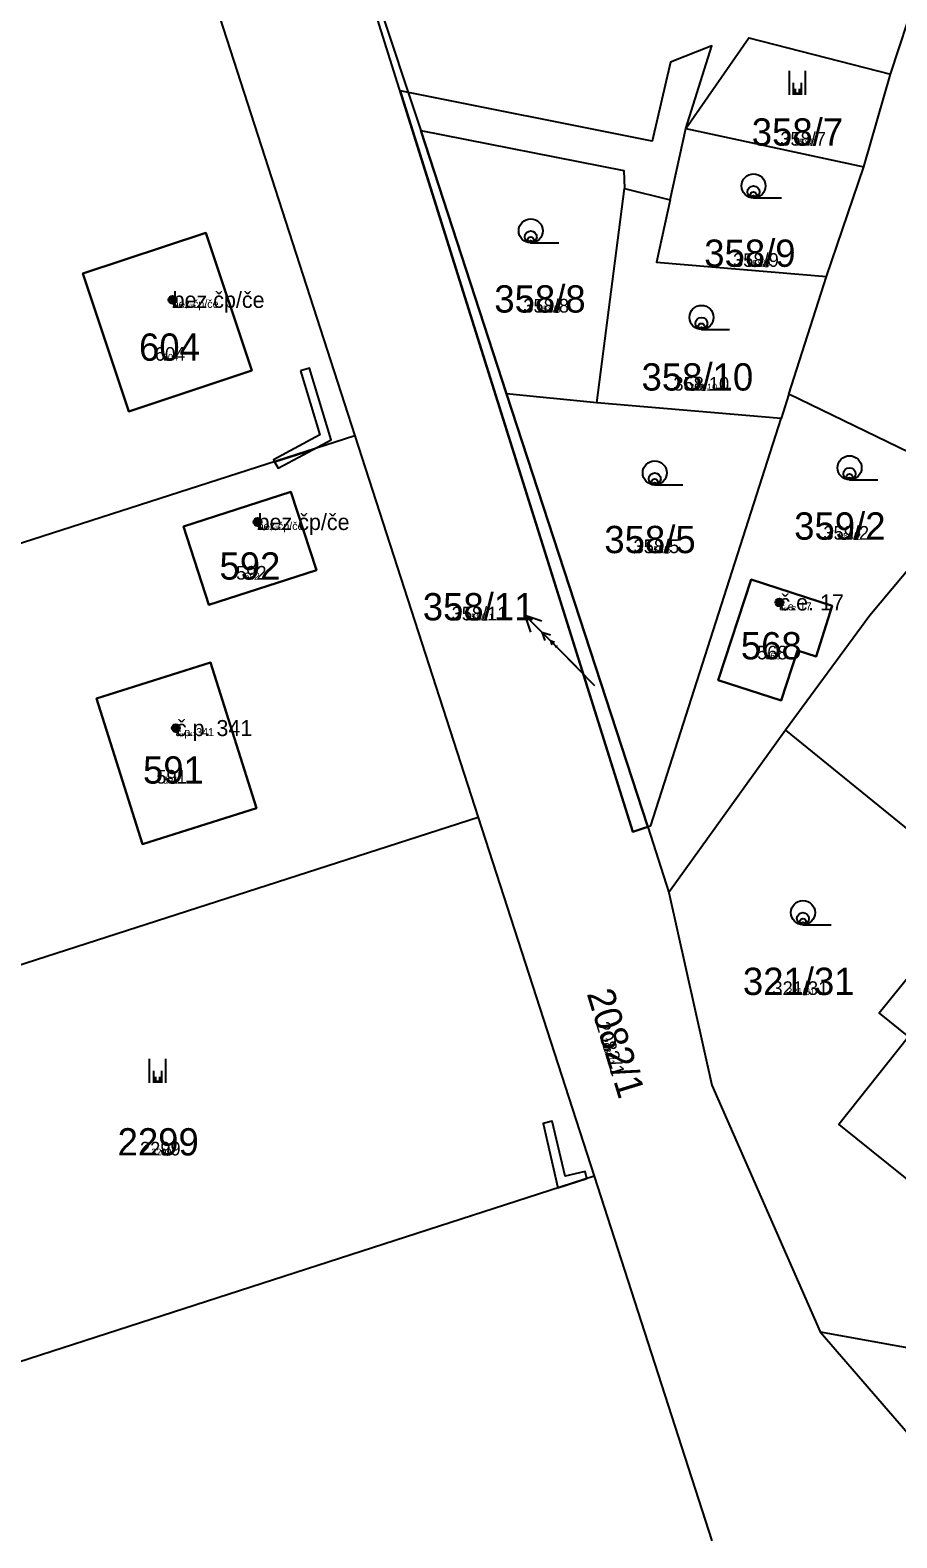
# Model space of a CAD drawing. Extents: x -744652 to -739090, y -980828 to -975855.
# Drawn here: x -742405.9 to -742351.9, y -979035.7 to -978941.8 of the extents above; entities that cross this region are included whole.
import ezdxf

# ---------------------------------------------------------------- set-up
doc = ezdxf.new("R2010")
doc.units = 0
for name, color, linetype in [('KAT_02_hranice parcel', 7, 'Continuous'), ('KAT_03_1000_st čísla parcelní', 7, 'Continuous'), ('KAT_03_1000_čísla parcelní', 7, 'Continuous'), ('KAT_03_1000_čísla popisná', 7, 'Continuous'), ('KAT_03_100_st čísla parcelní', 7, 'Continuous'), ('KAT_03_100_čísla parcelní', 7, 'Continuous'), ('KAT_03_100_čísla popisná', 7, 'Continuous'), ('KAT_03_250_st čísla parcelní', 7, 'Continuous'), ('KAT_03_250_čísla parcelní', 7, 'Continuous'), ('KAT_03_250_čísla popisná', 7, 'Continuous'), ('KAT_03_500_st čísla parcelní', 7, 'Continuous'), ('KAT_03_500_čísla parcelní', 7, 'Continuous'), ('KAT_03_500_čísla popisná', 7, 'Continuous'), ('KAT_05_1000_značky kultur', 7, 'Continuous'), ('KAT_05_100_značky kultur', 7, 'Continuous'), ('KAT_05_250_značky kultur', 7, 'Continuous'), ('KAT_05_500_značky kultur', 7, 'Continuous'), ('KAT_07_1000_značky budov', 7, 'Continuous'), ('KAT_07_100_značky budov', 7, 'Continuous'), ('KAT_07_500_značky budov', 7, 'Continuous'), ('KAT_10_věcná břemena', 7, 'Continuous'), ('KAT_12_pomocná šipka', 7, 'Continuous'), ('KAT_14_plocha_budovy', 7, 'Continuous')]:
    doc.layers.add(name, color=color, linetype=linetype)

msp = doc.modelspace()

# ---------------------------------------------------------------- linework, layer by layer
at = {"layer": 'KAT_02_hranice parcel'}
for p, q in [((-742391.18, -978919), (-742381.55, -978948.02)), ((-742352.31, -978944.52), (-742348.59, -978933.15)), ((-742395.24, -978937.4), (-742385.66, -978967.06)), ((-742353.98, -978950.28), (-742352.31, -978944.52)), ((-742366.03, -978952.34), (-742365.05, -978947.9)), ((-742365.05, -978947.9), (-742353.98, -978950.28)), ((-742381.55, -978948.02), (-742376.23, -978964.44)), ((-742356.29, -978957.13), (-742353.98, -978950.28)), ((-742370.6, -978964.99), (-742368.88, -978951.64)), ((-742368.88, -978951.64), (-742366.03, -978952.34)), ((-742358.65, -978964.45), (-742356.29, -978957.13)), ((-742370.6, -978964.99), (-742376.23, -978964.44)), ((-742376.23, -978964.44), (-742367.42, -978991.42)), ((-742358.65, -978964.45), (-742359.13, -978965.98)), ((-742346.86, -978970.19), (-742358.65, -978964.45)), ((-742359.13, -978965.98), (-742370.6, -978964.99)), ((-742385.66, -978967.06), (-742377.98, -978990.83)), ((-742358.86, -978985.4), (-742366.11, -978995.5)), ((-742358.86, -978985.4), (-742333.76, -979005.77)), ((-742377.98, -978990.83), (-742424.07, -979005.7)), ((-742377.98, -978990.83), (-742370.77, -979013.18)), ((-742367.42, -978991.42), (-742366.11, -978995.5)), ((-742370.77, -979013.18), (-742416.9, -979028.09)), ((-742370.77, -979013.18), (-742363.43, -979035.9)), ((-742356.7, -979022.87), (-742347.31, -979033.75))]:
    msp.add_line(p, q, dxfattribs=at)
for points in [[(-742367.42, -978991.42), (-742368.35, -978991.73), (-742391.18, -978919)], [(-742365.05, -978947.9), (-742361.13, -978942.26), (-742352.31, -978944.52)], [(-742381.55, -978948.02), (-742368.92, -978950.51), (-742368.88, -978951.64)], [(-742366.03, -978952.34), (-742366.89, -978956.22), (-742356.29, -978957.13)], [(-742394.94, -978954.4), (-742392.07, -978962.98), (-742399.73, -978965.53), (-742402.6, -978956.94), (-742394.94, -978954.4)], [(-742367.42, -978991.42), (-742367.24, -978991.34), (-742359.13, -978965.98)], [(-742385.66, -978967.06), (-742418.49, -978977.62), (-742431.69, -978981.87)], [(-742346.86, -978970.19), (-742353.6, -978978.24), (-742358.86, -978985.4)], [(-742389.65, -978970.55), (-742388.06, -978975.42), (-742394.75, -978977.59), (-742396.33, -978972.7), (-742389.65, -978970.55)], [(-742359.12, -978983.55), (-742363.04, -978982.28), (-742360.98, -978976.01), (-742355.94, -978977.64), (-742356.95, -978980.8), (-742358.1, -978980.42), (-742359.12, -978983.55)], [(-742398.89, -978992.5), (-742401.76, -978983.42), (-742394.65, -978981.17), (-742391.79, -978990.26), (-742398.89, -978992.5)], [(-742366.11, -978995.5), (-742363.44, -979007.5), (-742356.7, -979022.87)], [(-742341.51, -979015.59), (-742345.7, -979012.29), (-742346.66, -979011.52), (-742343.24, -979007.35), (-742346.77, -979004.52), (-742345.49, -979002.88), (-742346.69, -979001.94), (-742350, -978999.29), (-742353.02, -979003.02), (-742351.19, -979004.5), (-742355.53, -979009.96), (-742349.38, -979014.9), (-742349, -979014.44), (-742348.1, -979015.14), (-742344.85, -979018.06), (-742344.3, -979019.01)], [(-742356.7, -979022.87), (-742350.48, -979023.99), (-742348.33, -979024), (-742344.3, -979019.01)]]:
    msp.add_lwpolyline(points, dxfattribs=at)
at = {"layer": 'KAT_03_1000_čísla popisná'}
for centre in [(-742397.01, -978958.58), (-742397.01, -978958.58), (-742391.72, -978972.42), (-742391.72, -978972.42), (-742359.23, -978977.43), (-742359.23, -978977.43), (-742396.81, -978985.26), (-742396.81, -978985.26)]:
    msp.add_circle(centre, 0.25, dxfattribs=at)
at = {"layer": 'KAT_03_100_čísla popisná'}
for p, q in [((-742372.96, -978980.34), (-742373.172, -978980.128)), ((-742373.172, -978980.128), (-742373.066, -978980.163)), ((-742373.172, -978980.128), (-742373.137, -978980.234)), ((-742371.733, -978981.594), (-742371.956, -978981.366))]:
    msp.add_line(p, q, dxfattribs=at)
for centre in [(-742397.01, -978958.58), (-742397.01, -978958.58), (-742391.72, -978972.42), (-742391.72, -978972.42), (-742359.23, -978977.43), (-742359.23, -978977.43), (-742396.81, -978985.26), (-742396.81, -978985.26)]:
    msp.add_circle(centre, 0.025, dxfattribs=at)
at = {"layer": 'KAT_03_250_čísla popisná'}
for p, q in [((-742372.96, -978980.34), (-742374.021, -978979.279)), ((-742374.021, -978979.279), (-742373.49, -978979.456)), ((-742374.021, -978979.279), (-742373.844, -978979.81)), ((-742372.96, -978980.34), (-742373.491, -978979.809)), ((-742373.491, -978979.809), (-742373.225, -978979.898)), ((-742373.491, -978979.809), (-742373.402, -978980.075)), ((-742371.287, -978982.05), (-742372.402, -978980.91)), ((-742371.566, -978981.765), (-742372.124, -978981.195))]:
    msp.add_line(p, q, dxfattribs=at)
for centre in [(-742397.01, -978958.58), (-742397.01, -978958.58), (-742391.72, -978972.42), (-742391.72, -978972.42), (-742359.23, -978977.43), (-742359.23, -978977.43), (-742396.81, -978985.26), (-742396.81, -978985.26)]:
    msp.add_circle(centre, 0.0625, dxfattribs=at)
at = {"layer": 'KAT_03_500_čísla popisná'}
for p, q in [((-742372.96, -978980.34), (-742374.021, -978979.279)), ((-742374.021, -978979.279), (-742373.49, -978979.456)), ((-742374.021, -978979.279), (-742373.844, -978979.81)), ((-742371.287, -978982.05), (-742372.402, -978980.91))]:
    msp.add_line(p, q, dxfattribs=at)
for centre in [(-742397.01, -978958.58), (-742397.01, -978958.58), (-742391.72, -978972.42), (-742391.72, -978972.42), (-742359.23, -978977.43), (-742359.23, -978977.43), (-742396.81, -978985.26), (-742396.81, -978985.26)]:
    msp.add_circle(centre, 0.125, dxfattribs=at)
at = {"layer": 'KAT_05_1000_značky kultur'}
for p, q in [((-742358.611, -978945.81), (-742358.611, -978944.31)), ((-742357.61, -978945.81), (-742357.61, -978944.31)), ((-742360.843, -978952.23), (-742359.093, -978952.23)), ((-742374.713, -978955.03), (-742372.963, -978955.03)), ((-742364.083, -978960.42), (-742362.333, -978960.42)), ((-742366.993, -978970.11), (-742365.243, -978970.11)), ((-742354.863, -978969.79), (-742353.113, -978969.79)), ((-742357.763, -978997.51), (-742356.013, -978997.51)), ((-742398.441, -979007.36), (-742398.441, -979005.86)), ((-742397.44, -979007.36), (-742397.44, -979005.86))]:
    msp.add_line(p, q, dxfattribs=at)
for centre in [(-742360.843, -978951.48), (-742374.713, -978954.28), (-742364.083, -978959.67), (-742354.863, -978969.04), (-742366.993, -978969.36), (-742357.763, -978996.76)]:
    msp.add_circle(centre, 0.75, dxfattribs=at)
at = {"layer": 'KAT_05_100_značky kultur'}
for p, q in [((-742358.151, -978945.81), (-742358.151, -978945.66)), ((-742358.051, -978945.81), (-742358.051, -978945.66)), ((-742360.849, -978952.23), (-742360.674, -978952.23)), ((-742374.719, -978955.03), (-742374.544, -978955.03)), ((-742364.089, -978960.42), (-742363.914, -978960.42)), ((-742366.999, -978970.11), (-742366.824, -978970.11)), ((-742354.869, -978969.79), (-742354.694, -978969.79)), ((-742357.769, -978997.51), (-742357.594, -978997.51)), ((-742397.981, -979007.36), (-742397.981, -979007.21)), ((-742397.881, -979007.36), (-742397.881, -979007.21))]:
    msp.add_line(p, q, dxfattribs=at)
for centre in [(-742360.849, -978952.155), (-742374.719, -978954.955), (-742364.089, -978960.345), (-742366.999, -978970.035), (-742354.869, -978969.715), (-742357.769, -978997.435)]:
    msp.add_circle(centre, 0.075, dxfattribs=at)
at = {"layer": 'KAT_05_250_značky kultur'}
for p, q in [((-742358.228, -978945.81), (-742358.228, -978945.435)), ((-742357.978, -978945.81), (-742357.978, -978945.435)), ((-742360.848, -978952.23), (-742360.411, -978952.23)), ((-742374.718, -978955.03), (-742374.281, -978955.03)), ((-742364.088, -978960.42), (-742363.651, -978960.42)), ((-742366.998, -978970.11), (-742366.561, -978970.11)), ((-742354.868, -978969.79), (-742354.431, -978969.79)), ((-742357.768, -978997.51), (-742357.331, -978997.51)), ((-742398.058, -979007.36), (-742398.058, -979006.985)), ((-742397.807, -979007.36), (-742397.807, -979006.985))]:
    msp.add_line(p, q, dxfattribs=at)
for centre in [(-742360.848, -978952.042), (-742374.718, -978954.842), (-742364.088, -978960.232), (-742354.868, -978969.602), (-742366.998, -978969.922), (-742357.768, -978997.322)]:
    msp.add_circle(centre, 0.187, dxfattribs=at)
at = {"layer": 'KAT_05_500_značky kultur'}
for p, q in [((-742358.356, -978945.81), (-742358.356, -978945.06)), ((-742357.855, -978945.81), (-742357.855, -978945.06)), ((-742360.846, -978952.23), (-742359.971, -978952.23)), ((-742374.716, -978955.03), (-742373.841, -978955.03)), ((-742364.086, -978960.42), (-742363.211, -978960.42)), ((-742366.997, -978970.11), (-742366.122, -978970.11)), ((-742354.867, -978969.79), (-742353.992, -978969.79)), ((-742357.767, -978997.51), (-742356.892, -978997.51)), ((-742398.186, -979007.36), (-742398.186, -979006.61)), ((-742397.685, -979007.36), (-742397.685, -979006.61))]:
    msp.add_line(p, q, dxfattribs=at)
for centre in [(-742360.846, -978951.855), (-742374.716, -978954.655), (-742364.086, -978960.045), (-742366.996, -978969.735), (-742354.866, -978969.415), (-742357.766, -978997.135)]:
    msp.add_circle(centre, 0.375, dxfattribs=at)
at = {"layer": 'KAT_07_1000_značky budov'}
for centre in [(-742397.017, -978958.579), (-742391.727, -978972.419), (-742359.237, -978977.429), (-742396.817, -978985.259)]:
    msp.add_circle(centre, 0.175, dxfattribs=at)
at = {"layer": 'KAT_07_100_značky budov'}
for centre in [(-742397.011, -978958.58), (-742391.721, -978972.42), (-742359.231, -978977.43), (-742396.811, -978985.26)]:
    msp.add_circle(centre, 0.0175, dxfattribs=at)
at = {"layer": 'KAT_07_500_značky budov'}
for centre, radius in [((-742397.013, -978958.58), 0.0875), ((-742397.012, -978958.58), 0.0438), ((-742391.723, -978972.42), 0.0875), ((-742391.722, -978972.42), 0.0438), ((-742359.233, -978977.43), 0.0875), ((-742359.232, -978977.43), 0.0438), ((-742396.813, -978985.26), 0.0875), ((-742396.812, -978985.26), 0.0438)]:
    msp.add_circle(centre, radius, dxfattribs=at)
at = {"layer": 'KAT_10_věcná břemena'}
for points in [[(-742363.44, -978942.76), (-742366.01, -978943.77), (-742367.16, -978948.69), (-742382.85, -978945.55), (-742368.35, -978991.73), (-742367.42, -978991.42), (-742376.23, -978964.44), (-742381.55, -978948.02), (-742368.92, -978950.51), (-742368.88, -978951.64), (-742366.03, -978952.34), (-742365.05, -978947.9)], [(-742365.05, -978947.9), (-742363.44, -978942.76), (-742366.01, -978943.77), (-742367.16, -978948.69), (-742382.85, -978945.55), (-742368.35, -978991.73), (-742367.42, -978991.42), (-742376.23, -978964.44), (-742381.55, -978948.02), (-742368.92, -978950.51), (-742368.88, -978951.64), (-742366.03, -978952.34)], [(-742389.05, -978963.01), (-742387.85, -978966.99), (-742390.74, -978968.54), (-742390.67, -978968.67), (-742388.26, -978967.9), (-742387.13, -978967.29), (-742388.48, -978962.84)], [(-742388.26, -978967.9), (-742390.67, -978968.67), (-742390.45, -978969.07)], [(-742371.23, -979013.33), (-742371.33, -979012.89), (-742372.57, -979013.17), (-742373.37, -979009.75), (-742373.95, -979009.89), (-742373.03, -979013.91)]]:
    msp.add_lwpolyline(points, close=True, dxfattribs=at)
at = {"layer": 'KAT_12_pomocná šipka'}
for p, q in [((-742372.96, -978980.34), (-742375.082, -978978.218)), ((-742375.082, -978978.218), (-742374.02, -978978.572)), ((-742375.082, -978978.218), (-742374.728, -978979.28)), ((-742370.73, -978982.62), (-742372.96, -978980.34))]:
    msp.add_line(p, q, dxfattribs=at)
at = {"layer": 'KAT_14_plocha_budovy'}
for points in [[(-742402.6, -978956.94), (-742399.73, -978965.53), (-742392.07, -978962.98), (-742394.94, -978954.4)], [(-742396.33, -978972.7), (-742394.75, -978977.59), (-742388.06, -978975.42), (-742389.65, -978970.55)], [(-742363.04, -978982.28), (-742359.12, -978983.55), (-742358.1, -978980.42), (-742356.95, -978980.8), (-742355.94, -978977.64), (-742360.98, -978976.01)], [(-742401.76, -978983.42), (-742398.89, -978992.5), (-742391.79, -978990.26), (-742394.65, -978981.17)], [(-742355.53, -979009.96), (-742349.38, -979014.9), (-742349, -979014.44), (-742348.1, -979015.14), (-742345.7, -979012.29), (-742346.66, -979011.52), (-742343.24, -979007.35), (-742346.77, -979004.52), (-742347.96, -979003.56), (-742346.69, -979001.94), (-742350, -978999.29), (-742353.02, -979003.02), (-742351.19, -979004.5)]]:
    msp.add_lwpolyline(points, close=True, dxfattribs=at)

# ---------------------------------------------------------------- texts
at = {"layer": 'KAT_03_1000_st čísla parcelní'}
for s, p in [('604', (-742399.104, -978962.37)), ('592', (-742394.094, -978976.01)), ('568', (-742361.634, -978980.98)), ('591', (-742398.854, -978988.72))]:
    msp.add_text(s, height=1.7, dxfattribs=at).set_placement(p)
at = {"layer": 'KAT_03_1000_čísla parcelní'}
for s, p in [('358/7', (-742360.953, -978948.97)), ('358/9', (-742363.913, -978956.52)), ('358/8', (-742376.983, -978959.37)), ('358/10', (-742367.815, -978964.23)), ('359/2', (-742358.313, -978973.52)), ('358/5', (-742370.133, -978974.36)), ('358/11', (-742381.435, -978978.55)), ('321/31', (-742361.505, -979001.89)), ('2299', (-742400.437, -979011.89))]:
    msp.add_text(s, height=1.7, dxfattribs=at).set_placement(p)
msp.add_text('2082/1', height=1.7, rotation=287, dxfattribs=at).set_placement((-742371.239, -979001.797))
at = {"layer": 'KAT_03_1000_čísla popisná'}
for s, height, p in [('bez čp/če', 1, (-742397.01, -978959.08)), ('604', 0.017, (-742397.143, -978962.37)), ('bez čp/če', 1, (-742391.72, -978972.92)), ('592', 0.017, (-742392.04, -978976.01)), ('č.e. 17', 1, (-742359.23, -978977.93)), ('568', 0.017, (-742359.633, -978980.98)), ('č.p. 341', 1, (-742396.81, -978985.76)), ('591', 0.017, (-742397.218, -978988.72))]:
    msp.add_text(s, height=height, dxfattribs=at).set_placement(p)
at = {"layer": 'KAT_03_100_st čísla parcelní'}
for s, p in [('604', (-742397.321, -978962.37)), ('592', (-742392.227, -978976.01)), ('568', (-742359.815, -978980.98)), ('591', (-742397.366, -978988.72))]:
    msp.add_text(s, height=0.17, dxfattribs=at).set_placement(p)
at = {"layer": 'KAT_03_100_čísla parcelní'}
for s, p in [('358/7', (-742357.755, -978948.97)), ('358/9', (-742360.679, -978956.52)), ('358/8', (-742373.73, -978959.37)), ('358/10', (-742364.249, -978964.23)), ('358/5', (-742366.856, -978974.36)), ('359/2', (-742355.036, -978973.52)), ('358/11', (-742378.207, -978978.55)), ('321/31', (-742358.198, -979001.89)), ('2299', (-742397.925, -979011.89))]:
    msp.add_text(s, height=0.17, dxfattribs=at).set_placement(p)
msp.add_text('2082/1', height=0.17, rotation=287, dxfattribs=at).set_placement((-742370.193, -979005.218))
at = {"layer": 'KAT_03_100_čísla popisná'}
for s, height, p in [('bez čp/če', 0.1, (-742397.01, -978959.08)), ('604', 0.0017, (-742397.125, -978962.37)), ('bez čp/če', 0.1, (-742391.72, -978972.92)), ('592', 0.0017, (-742392.021, -978976.01)), ('č.e. 17', 0.1, (-742359.23, -978977.93)), ('568', 0.0017, (-742359.615, -978980.98)), ('č.p. 341', 0.1, (-742396.81, -978985.76)), ('591', 0.0017, (-742397.203, -978988.72))]:
    msp.add_text(s, height=height, dxfattribs=at).set_placement(p)
at = {"layer": 'KAT_03_250_st čísla parcelní'}
for s, p in [('604', (-742397.618, -978962.37)), ('592', (-742392.538, -978976.01)), ('568', (-742360.118, -978980.98)), ('591', (-742397.614, -978988.72))]:
    msp.add_text(s, height=0.425, dxfattribs=at).set_placement(p)
at = {"layer": 'KAT_03_250_čísla parcelní'}
for s, p in [('358/7', (-742358.288, -978948.97)), ('358/9', (-742361.218, -978956.52)), ('358/8', (-742374.273, -978959.37)), ('358/10', (-742364.844, -978964.23)), ('359/2', (-742355.582, -978973.52)), ('358/5', (-742367.402, -978974.36)), ('358/11', (-742378.745, -978978.55)), ('321/31', (-742358.749, -979001.89)), ('2299', (-742398.344, -979011.89))]:
    msp.add_text(s, height=0.425, dxfattribs=at).set_placement(p)
msp.add_text('2082/1', height=0.425, rotation=287, dxfattribs=at).set_placement((-742370.367, -979004.648))
at = {"layer": 'KAT_03_250_čísla popisná'}
for s, height, p in [('bez čp/če', 0.25, (-742397.01, -978959.08)), ('604', 0.00425, (-742397.128, -978962.37)), ('bez čp/če', 0.25, (-742391.72, -978972.92)), ('592', 0.00425, (-742392.025, -978976.01)), ('č.e. 17', 0.25, (-742359.23, -978977.93)), ('568', 0.00425, (-742359.618, -978980.98)), ('č.p. 341', 0.25, (-742396.81, -978985.76)), ('591', 0.00425, (-742397.205, -978988.72))]:
    msp.add_text(s, height=height, dxfattribs=at).set_placement(p)
at = {"layer": 'KAT_03_500_st čísla parcelní'}
for s, p in [('604', (-742398.114, -978962.37)), ('592', (-742393.057, -978976.01)), ('568', (-742360.623, -978980.98)), ('591', (-742398.028, -978988.72))]:
    msp.add_text(s, height=0.85, dxfattribs=at).set_placement(p)
at = {"layer": 'KAT_03_500_čísla parcelní'}
for s, p in [('358/7', (-742359.176, -978948.97)), ('358/9', (-742362.116, -978956.52)), ('358/8', (-742375.176, -978959.37)), ('358/10', (-742365.834, -978964.23)), ('359/2', (-742356.493, -978973.52)), ('358/5', (-742368.313, -978974.36)), ('358/11', (-742379.641, -978978.55)), ('321/31', (-742359.668, -979001.89)), ('2299', (-742399.042, -979011.89))]:
    msp.add_text(s, height=0.85, dxfattribs=at).set_placement(p)
msp.add_text('2082/1', height=0.85, rotation=287, dxfattribs=at).set_placement((-742370.658, -979003.698))
at = {"layer": 'KAT_03_500_čísla popisná'}
for s, height, p in [('bez čp/če', 0.5, (-742397.01, -978959.08)), ('604', 0.0085, (-742397.133, -978962.37)), ('bez čp/če', 0.5, (-742391.72, -978972.92)), ('592', 0.0085, (-742392.03, -978976.01)), ('č.e. 17', 0.5, (-742359.23, -978977.93)), ('568', 0.0085, (-742359.623, -978980.98)), ('č.p. 341', 0.5, (-742396.81, -978985.76)), ('591', 0.0085, (-742397.209, -978988.72))]:
    msp.add_text(s, height=height, dxfattribs=at).set_placement(p)

doc.saveas('drawing.dxf')
